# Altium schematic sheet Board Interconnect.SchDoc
size A3; Date: 24.10.2012; CheckedBy: MRipel; Author: Burmeister; Organization: RUETZ TECHNOLOGIES; Address1: Walter-Gropius-Str. 17; Address2: 80807; Address3: München; Address4: Germany; DocumentNumber: 2; Revision: 1.0; SheetNumber: 2; SheetTotal: 10; Abteilung: Hard/Software Entwicklung; Sachnummer: DCB-25863; Datum_V1: 24.10.2012; Version_V1: 1.0; Ersteller_V1: Burmeister; Geprueft_V1: MRipel
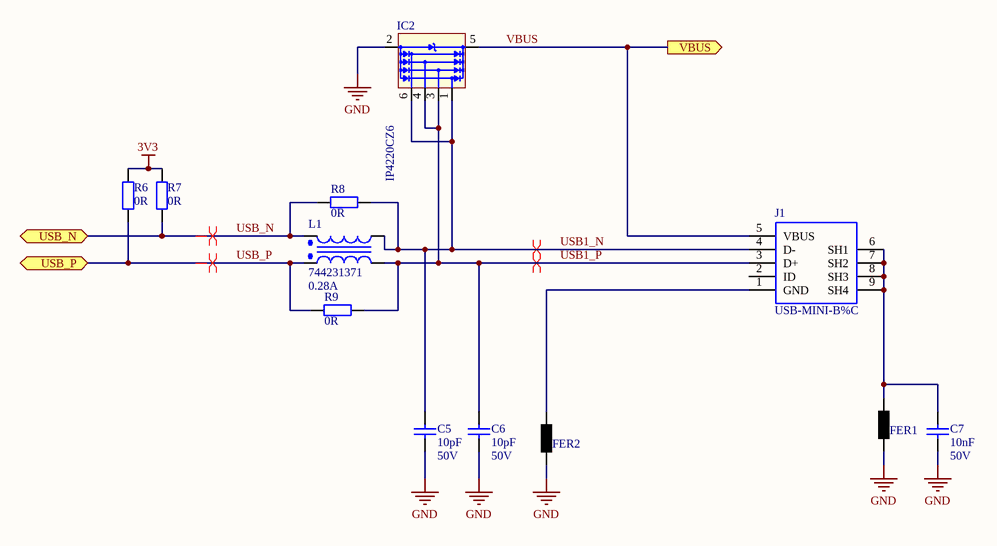
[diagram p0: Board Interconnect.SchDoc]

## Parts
C5  L_Spannung: 50V  [RLCDT_0603]  (hidden comment: 10pF)
C6  L_Spannung: 50V  [RLCDT_0603]  (hidden comment: 10pF)
C7  L_Spannung: 50V  [RLCDT_0603]  (hidden comment: 10nF)
FER1  742792651  [RLCDT_0603]  (value not drawn)
FER2  742792651  [RLCDT_0603]  (value not drawn)
IC2  IP4220CZ6  [ESD_SOT457]
J1  USB-MINI-B%C  [USB-MINI-B_2]
L1  M_Strom: 0.28A  [RLCDT_CMC_WÜRTH_CNSW_0805]  (hidden comment: 744231371)
R6  0R  [RLCDT_0603]
R7  0R  [RLCDT_0603]
R8  0R  [RLCDT_0603]
R9  0R  [RLCDT_0603]

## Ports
USB_N (bidir), USB_P (bidir), VBUS (out)

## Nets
3V3: R6.1 R7.1
GND: C5.1 C6.1 C7.2 FER1.1 FER2.2 IC2.2(GND)
USB1_N: C5.2 IC2.1(I/O_1) IC2.6(I/O_4) J1.4(D-) L1.3 R8.1
USB1_P: C6.2 IC2.3(I/O_2) IC2.4(I/O_3) J1.3(D+) L1.2 R9.1
USB_N: L1.4 R7.2 R8.2 ; port USB_N
USB_P: L1.1 R6.2 R9.2 ; port USB_P
VBUS: IC2.5(Vp) J1.5(VBUS) ; port VBUS
NetC7_1: C7.1 FER1.2 J1.6(SH1) J1.7(SH2) J1.8(SH3) J1.9(SH4)
NetFER2_1: FER2.1 J1.1(GND)

Not connected (* = marked no-connect by the designer): J1 2(ID)

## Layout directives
differential pair: USB1_N, USB1_P, USB_N, USB_P

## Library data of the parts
C5 C6 = C_KERAMIK: Kondensator, Keramik; W_Erstellt: MRipel; H_Temp_min: -55°C; I_Temp_max: 125°C; D_Hersteller: AVX; E_Herstellerbezeichnung: 06035A100JAT2A; B_Bestellnummer: 499110RL; J_Richtpreis_10: 0.062; K_Richtpreis_100: 0.04; G_Wird_beigestellt: Nein; A_Update_From_DB: Ja; F_Lagernummer: keine; A_Charakteristik: NPO; A_Database_ID: RLCDT_C_Ker_50
C7 = C_KERAMIK: Kondensator, Keramik; W_Erstellt: MRipel; H_Temp_min: -55°C; I_Temp_max: 125°C; D_Hersteller: KEMET; E_Herstellerbezeichnung: C0603C103K5RAC; B_Bestellnummer: 1414609; J_Richtpreis_10: 0.02; K_Richtpreis_100: 0.011; G_Wird_beigestellt: Nein; A_Update_From_DB: Ja; F_Lagernummer: keine; A_Charakteristik: X7R; A_Database_ID: RLCDT_C_Ker_02
FER1 FER2 = FER: Ferrit; W_Erstellt: MRipel; M_Strom: 1A; H_Temp_min: -55°C; I_Temp_max: 125°C; D_Hersteller: Würth Elektronik; G_Wird_beigestellt: Nein; A_Update_From_DB: Ja; F_Lagernummer: keine; A_Charakteristik: 600R/100MHz; A_Database_ID: RLCDT_FER_12
IC2 = ESD_IP4220CZ6: ESD, USB, level4, 8kV; W_Erstellt: Scheuring; B_Bestellnummer: 1506629; X_Datenblatt: S:\Datenblaetter\_RUETZ_ALTIUM_LIB\RUETZ_ESD\ESD_IP4220CZ6.pdf; L_Spannung: 5V5; D_Hersteller: NXP; J_Richtpreis_10: 0.3; K_Richtpreis_100: 0.26; W_Geprueft: Bitte Ausfüllen; H_Temp_min: -40°C; I_Temp_max: 85°C; W_Info: optional; G_Wird_beigestellt: Nein; A_Update_From_DB: Ja; F_Lagernummer: keine; A_DATABASE_ID: ESD_9
L1 = L_CMC: Common Mode Choke, Spule; W_Erstellt: MRipel; L_Spannung: 50V; H_Temp_min: -40°C; I_Temp_max: 125°C; D_Hersteller: Würth Elektronik; J_Richtpreis_10: 0.75; K_Richtpreis_100: 0.65; G_Wird_beigestellt: Nein; A_Update_From_DB: Ja; F_Lagernummer: keine; A_Database_ID: RLCDT_L_1; A_Charakteristik: 370R/100MHz
R6-R9 = R: Widerstand; W_Erstellt: MRipel; A_Wichtiger_Hinweis: optional; L_Spannung: 50V; H_Temp_min: ?°C; J_Richtpreis_10: 0,00; G_Wird_beigestellt: Nein; A_Update_From_DB: Ja; A_Database_ID: not updated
